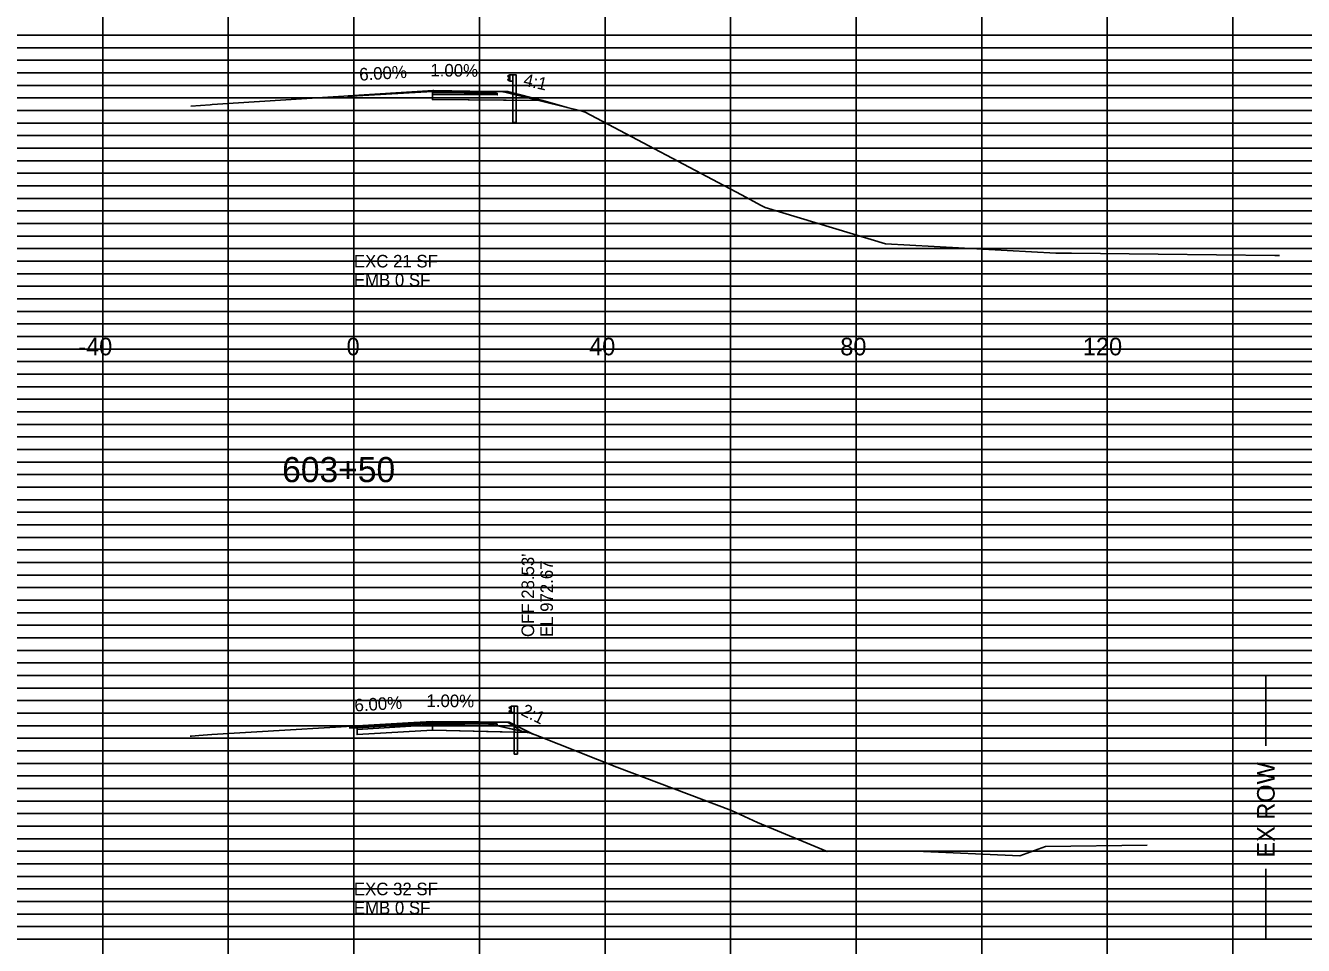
# Model space of a CAD drawing. Extents: x 2313580 to 2322968, y 282099 to 303247.
# Drawn here: x 2318731.4 to 2318934.9, y 287726.7 to 287873.2 of the extents above; entities that cross this region are included whole.
import ezdxf

# ---------------------------------------------------------------- set-up
doc = ezdxf.new("R2010")
doc.units = 0
for name, color, linetype in [('DESIGN - CENTERLINE - Proposed', 7, 'Continuous'), ('DESIGN - DRAINAGE - Text', 7, 'Continuous'), ('DESIGN - EARTHWORK - Excavation Limit Lines', 7, 'Continuous'), ('DESIGN - EARTHWORK - Shapes', 7, 'Continuous'), ('DESIGN - SCRATCH - User 1', 7, 'Continuous'), ('DESIGN - SHEET - Light Grid', 7, 'Continuous'), ('DESIGN - SHEET - Linework', 7, 'Continuous'), ('DESIGN - TYPICAL - Finished Grade and Subgrade', 7, 'Continuous'), ('DESIGN - TYPICAL - Finished Grade Slopes Text', 7, 'Continuous'), ('DESIGN - TYPICAL - Guardrail', 7, 'Continuous'), ('DESIGN - TYPICAL - Text', 7, 'Continuous'), ('Scratch Level', 7, 'Continuous'), ('SURVEY - GROUND - Top of Ground', 7, 'Continuous'), ('SURVEY - PROPERTY - ROW Lines Text', 7, 'Continuous')]:
    doc.layers.add(name, color=color, linetype=linetype)

# ---------------------------------------------------------------- blocks, each defined once
blk = doc.blocks.new('GRTYP')
at = {"layer": 'DESIGN - CENTERLINE - Proposed'}
for p, q in [((0.162, 0.37), (0.162, 0.37)), ((0.162, 0.37), (0.162, 0.37)), ((0.264, 0.37), (0.264, 0.37)), ((0.264, 0.37), (0.264, 0.37))]:
    blk.add_line(p, q, dxfattribs=at)
for points in [[(0.059, 0.567), (0.04, 0.563), (0.004, 0.539), (0, 0.531), (0.004, 0.523), (0.055, 0.492), (0.059, 0.484), (0.059, 0.464), (0.055, 0.456), (0.004, 0.425), (0, 0.417), (0.004, 0.409), (0.04, 0.385), (0.059, 0.382)], [(0.162, 0.374), (0.059, 0.374), (0.059, 0.574), (0.162, 0.574)], [(0.264, -0.126), (0.264, 0.574), (0.162, 0.574), (0.162, -0.075)], [(0.162, -0.075), (0.162, -0.949), (0.264, -0.949), (0.264, -0.122)]]:
    blk.add_lwpolyline(points, dxfattribs=at)

msp = doc.modelspace()

# ---------------------------------------------------------------- linework, layer by layer
msp.add_line((2318796.2, 287862.24), (2318806.51, 287862.15))
at = {"layer": 'DESIGN - EARTHWORK - Shapes'}
for points in [[(2318782.75, 287861.99), (2318795.48, 287862.8), (2318796.26, 287862.85), (2318796.41, 287862.84), (2318802.13, 287862.74), (2318807.38, 287862.64), (2318807.53, 287862.64), (2318807.94, 287862.56), (2318813.17, 287861.25), (2318796.2, 287861.41), (2318796.2, 287862.24), (2318796.2, 287862.49), (2318796.2, 287862.7), (2318784.2, 287861.98), (2318782.75, 287861.89)], [(2318813.17, 287861.25), (2318817.64, 287860.14), (2318813.77, 287861.25)], [(2318783.06, 287761.57), (2318791.5, 287762.07), (2318794.35, 287762.24), (2318804.18, 287762.1), (2318804.63, 287762.1), (2318804.66, 287762.09), (2318811.26, 287760.61), (2318796.19, 287760.97), (2318784.19, 287760.25), (2318784.19, 287761.08), (2318784.19, 287761.33), (2318783.06, 287761.27), (2318783.06, 287761.47)], [(2318811.26, 287760.61), (2318811.84, 287760.48), (2318812.21, 287760.34), (2318811.7, 287760.6)]]:
    msp.add_lwpolyline(points, close=True, dxfattribs=at)
at = {"layer": 'DESIGN - SCRATCH - User 1'}
for points in [[(2318806.2, 287862.7), (2318808.2, 287862.68), (2318810.77, 287861.85)], [(2318806.2, 287862.7), (2318808.2, 287862.68), (2318810.77, 287861.85)], [(2318806.2, 287862.7), (2318808.2, 287862.68), (2318810.77, 287861.85)], [(2318806.2, 287862.7), (2318808.2, 287862.68), (2318810.77, 287861.85)], [(2318806.19, 287762.26), (2318808.19, 287762.24), (2318810.33, 287760.82)], [(2318806.19, 287762.26), (2318808.19, 287762.24), (2318810.33, 287760.82)], [(2318806.19, 287762.26), (2318808.19, 287762.24), (2318810.33, 287760.82)], [(2318806.19, 287762.26), (2318808.19, 287762.24), (2318810.33, 287760.82)]]:
    msp.add_lwpolyline(points, dxfattribs=at)
at = {"layer": 'DESIGN - SHEET - Light Grid'}
for p, q in [((2318623.68, 287871.67), (2318783.68, 287871.67)), ((2318783.68, 287871.67), (2318943.68, 287871.67)), ((2318623.68, 287869.67), (2318783.68, 287869.67)), ((2318783.68, 287869.67), (2318943.68, 287869.67)), ((2318623.68, 287865.67), (2318783.68, 287865.67)), ((2318783.68, 287865.67), (2318943.68, 287865.67)), ((2318623.68, 287863.67), (2318783.68, 287863.67)), ((2318783.68, 287863.67), (2318943.68, 287863.67)), ((2318623.68, 287861.67), (2318783.68, 287861.67)), ((2318783.68, 287861.67), (2318943.68, 287861.67)), ((2318623.68, 287859.67), (2318783.68, 287859.67)), ((2318783.68, 287859.67), (2318943.68, 287859.67)), ((2318623.68, 287857.67), (2318783.68, 287857.67)), ((2318783.68, 287857.67), (2318943.68, 287857.67)), ((2318623.68, 287855.67), (2318783.68, 287855.67)), ((2318783.68, 287855.67), (2318943.68, 287855.67)), ((2318623.68, 287853.67), (2318783.68, 287853.67)), ((2318783.68, 287853.67), (2318943.68, 287853.67)), ((2318623.68, 287851.67), (2318783.68, 287851.67)), ((2318783.68, 287851.67), (2318943.68, 287851.67)), ((2318623.68, 287849.67), (2318783.68, 287849.67)), ((2318783.68, 287849.67), (2318943.68, 287849.67)), ((2318623.68, 287845.67), (2318783.68, 287845.67)), ((2318783.68, 287845.67), (2318943.68, 287845.67)), ((2318623.68, 287843.67), (2318783.68, 287843.67)), ((2318783.68, 287843.67), (2318943.68, 287843.67)), ((2318623.68, 287841.67), (2318783.68, 287841.67)), ((2318783.68, 287841.67), (2318943.68, 287841.67)), ((2318623.68, 287839.67), (2318783.68, 287839.67)), ((2318783.68, 287839.67), (2318943.68, 287839.67)), ((2318623.68, 287837.67), (2318783.68, 287837.67)), ((2318783.68, 287837.67), (2318943.68, 287837.67)), ((2318623.68, 287835.67), (2318783.68, 287835.67)), ((2318783.68, 287835.67), (2318943.68, 287835.67)), ((2318623.68, 287833.67), (2318783.68, 287833.67)), ((2318783.68, 287833.67), (2318943.68, 287833.67)), ((2318623.68, 287831.67), (2318783.68, 287831.67)), ((2318783.68, 287831.67), (2318943.68, 287831.67)), ((2318623.68, 287829.67), (2318783.68, 287829.67)), ((2318783.68, 287829.67), (2318943.68, 287829.67)), ((2318623.68, 287825.67), (2318783.68, 287825.67)), ((2318783.68, 287825.67), (2318943.68, 287825.67)), ((2318623.68, 287823.67), (2318783.68, 287823.67)), ((2318783.68, 287823.67), (2318943.68, 287823.67)), ((2318623.68, 287821.67), (2318783.68, 287821.67)), ((2318783.68, 287821.67), (2318943.68, 287821.67)), ((2318623.68, 287819.67), (2318783.68, 287819.67)), ((2318783.68, 287819.67), (2318943.68, 287819.67)), ((2318623.68, 287817.67), (2318783.68, 287817.67)), ((2318783.68, 287817.67), (2318943.68, 287817.67)), ((2318623.68, 287815.67), (2318783.68, 287815.67)), ((2318783.68, 287815.67), (2318943.68, 287815.67)), ((2318623.68, 287813.67), (2318783.68, 287813.67)), ((2318623.68, 287811.67), (2318783.68, 287811.67)), ((2318783.68, 287813.67), (2318943.68, 287813.67)), ((2318783.68, 287811.67), (2318943.68, 287811.67)), ((2318623.68, 287809.67), (2318783.68, 287809.67)), ((2318783.68, 287809.67), (2318943.68, 287809.67)), ((2318623.68, 287805.67), (2318783.68, 287805.67)), ((2318783.68, 287805.67), (2318943.68, 287805.67)), ((2318623.68, 287803.67), (2318783.68, 287803.67)), ((2318783.68, 287803.67), (2318943.68, 287803.67)), ((2318623.68, 287801.67), (2318783.68, 287801.67)), ((2318783.68, 287801.67), (2318943.68, 287801.67)), ((2318623.68, 287799.67), (2318783.68, 287799.67)), ((2318783.68, 287799.67), (2318943.68, 287799.67)), ((2318623.68, 287797.67), (2318783.68, 287797.67)), ((2318783.68, 287797.67), (2318943.68, 287797.67)), ((2318623.68, 287795.67), (2318783.68, 287795.67)), ((2318783.68, 287795.67), (2318943.68, 287795.67)), ((2318623.68, 287793.67), (2318783.68, 287793.67)), ((2318783.68, 287793.67), (2318943.68, 287793.67)), ((2318623.68, 287791.67), (2318783.68, 287791.67)), ((2318783.68, 287791.67), (2318943.68, 287791.67)), ((2318623.68, 287789.67), (2318783.68, 287789.67)), ((2318783.68, 287789.67), (2318943.68, 287789.67)), ((2318623.68, 287785.67), (2318783.68, 287785.67)), ((2318783.68, 287785.67), (2318943.68, 287785.67)), ((2318623.68, 287783.67), (2318783.68, 287783.67)), ((2318783.68, 287783.67), (2318943.68, 287783.67)), ((2318623.68, 287781.67), (2318783.68, 287781.67)), ((2318783.68, 287781.67), (2318943.68, 287781.67)), ((2318623.68, 287779.67), (2318783.68, 287779.67)), ((2318783.68, 287779.67), (2318943.68, 287779.67)), ((2318623.68, 287777.67), (2318783.68, 287777.67)), ((2318783.68, 287777.67), (2318943.68, 287777.67)), ((2318623.68, 287775.67), (2318783.68, 287775.67)), ((2318783.68, 287775.67), (2318943.68, 287775.67)), ((2318623.68, 287773.67), (2318783.68, 287773.67)), ((2318783.68, 287773.67), (2318943.68, 287773.67)), ((2318623.68, 287771.67), (2318783.68, 287771.67)), ((2318783.68, 287771.67), (2318943.68, 287771.67)), ((2318623.68, 287769.67), (2318783.68, 287769.67)), ((2318783.68, 287769.67), (2318943.68, 287769.67)), ((2318623.68, 287765.67), (2318783.68, 287765.67)), ((2318783.68, 287765.67), (2318943.68, 287765.67)), ((2318623.68, 287763.67), (2318783.68, 287763.67)), ((2318783.68, 287763.67), (2318943.68, 287763.67)), ((2318623.68, 287761.67), (2318783.68, 287761.67)), ((2318783.68, 287761.67), (2318943.68, 287761.67)), ((2318623.68, 287759.67), (2318783.68, 287759.67)), ((2318783.68, 287759.67), (2318943.68, 287759.67)), ((2318623.68, 287757.67), (2318783.68, 287757.67)), ((2318783.68, 287757.67), (2318943.68, 287757.67)), ((2318623.68, 287755.67), (2318783.68, 287755.67)), ((2318783.68, 287755.67), (2318943.68, 287755.67)), ((2318623.68, 287753.67), (2318783.68, 287753.67)), ((2318783.68, 287753.67), (2318943.68, 287753.67)), ((2318623.68, 287751.67), (2318783.68, 287751.67)), ((2318783.68, 287751.67), (2318943.68, 287751.67)), ((2318623.68, 287749.67), (2318783.68, 287749.67)), ((2318783.68, 287749.67), (2318943.68, 287749.67)), ((2318623.68, 287745.67), (2318783.68, 287745.67)), ((2318783.68, 287745.67), (2318943.68, 287745.67)), ((2318623.68, 287743.67), (2318783.68, 287743.67)), ((2318783.68, 287743.67), (2318943.68, 287743.67)), ((2318623.68, 287741.67), (2318783.68, 287741.67)), ((2318783.68, 287741.67), (2318943.68, 287741.67)), ((2318623.68, 287739.67), (2318783.68, 287739.67)), ((2318783.68, 287739.67), (2318943.68, 287739.67)), ((2318623.68, 287737.67), (2318783.68, 287737.67)), ((2318783.68, 287737.67), (2318943.68, 287737.67)), ((2318623.68, 287735.67), (2318783.68, 287735.67)), ((2318783.68, 287735.67), (2318943.68, 287735.67)), ((2318623.68, 287733.67), (2318783.68, 287733.67)), ((2318783.68, 287733.67), (2318943.68, 287733.67)), ((2318623.68, 287731.67), (2318783.68, 287731.67)), ((2318783.68, 287731.67), (2318943.68, 287731.67)), ((2318623.68, 287729.67), (2318783.68, 287729.67)), ((2318783.68, 287729.67), (2318943.68, 287729.67))]:
    msp.add_line(p, q, dxfattribs=at)
at = {"layer": 'DESIGN - SHEET - Linework'}
for p, q in [((2318743.68, 287587.67), (2318743.68, 288007.67)), ((2318763.68, 287587.67), (2318763.68, 288007.67)), ((2318783.68, 287587.67), (2318783.68, 288007.67)), ((2318803.68, 287587.67), (2318803.68, 288007.67)), ((2318823.68, 287587.67), (2318823.68, 288007.67)), ((2318843.68, 287587.67), (2318843.68, 288007.67)), ((2318863.68, 287587.67), (2318863.68, 288007.67)), ((2318883.68, 287587.67), (2318883.68, 288007.67)), ((2318903.68, 287587.67), (2318903.68, 288007.67)), ((2318923.68, 287587.67), (2318923.68, 288007.67)), ((2318463.68, 287867.67), (2319103.68, 287867.67)), ((2318463.68, 287847.67), (2319103.68, 287847.67)), ((2318463.68, 287827.67), (2319103.68, 287827.67)), ((2318463.68, 287807.67), (2319103.68, 287807.67)), ((2318463.68, 287787.67), (2319103.68, 287787.67)), ((2318463.68, 287767.67), (2319103.68, 287767.67)), ((2318463.68, 287747.67), (2319103.68, 287747.67)), ((2318463.68, 287727.67), (2319103.68, 287727.67))]:
    msp.add_line(p, q, dxfattribs=at)
at = {"layer": 'DESIGN - TYPICAL - Finished Grade and Subgrade'}
for points in [[(2318782.75, 287861.99), (2318784.02, 287862.07), (2318784.2, 287862.08), (2318794.7, 287862.71), (2318796.2, 287862.8), (2318804.95, 287862.72), (2318806.2, 287862.7), (2318807.95, 287862.69), (2318808.2, 287862.68), (2318808.49, 287862.61), (2318813.77, 287861.25), (2318817.64, 287860.14)], [(2318783.06, 287761.57), (2318783.34, 287761.59), (2318784.19, 287761.64), (2318793.21, 287762.18), (2318796.19, 287762.36), (2318803.7, 287762.29), (2318806.19, 287762.26), (2318807.69, 287762.25), (2318808.42, 287762.24), (2318812.21, 287760.34)]]:
    msp.add_lwpolyline(points, dxfattribs=at)
for points in [[(2318784.2, 287862.08), (2318796.2, 287862.8), (2318796.2, 287862.7), (2318784.2, 287861.98)], [(2318796.2, 287862.8), (2318806.2, 287862.7), (2318806.2, 287862.6), (2318796.2, 287862.7)], [(2318796.2, 287862.24), (2318806.51, 287862.15), (2318806.51, 287862.4), (2318806.3, 287862.4), (2318806.3, 287862.6), (2318806.2, 287862.6), (2318806.2, 287862.7), (2318808.2, 287862.68), (2318813.77, 287861.25), (2318796.2, 287861.41)], [(2318796.2, 287862.7), (2318806.3, 287862.6), (2318806.3, 287862.4), (2318796.2, 287862.49)], [(2318784.2, 287862.08), (2318782.75, 287861.99), (2318782.75, 287861.89), (2318784.2, 287861.98)], [(2318796.2, 287862.49), (2318806.51, 287862.4), (2318806.51, 287862.15), (2318796.2, 287862.24)], [(2318784.19, 287761.64), (2318783.06, 287761.57), (2318783.06, 287761.47), (2318784.19, 287761.54)], [(2318784.19, 287761.54), (2318784.19, 287761.33), (2318783.06, 287761.27), (2318783.06, 287761.47)], [(2318784.19, 287761.64), (2318796.19, 287762.36), (2318796.19, 287762.26), (2318784.19, 287761.54)], [(2318784.19, 287761.54), (2318796.19, 287762.26), (2318796.19, 287762.05), (2318784.19, 287761.33)], [(2318784.19, 287761.33), (2318796.19, 287762.05), (2318796.19, 287761.8), (2318784.19, 287761.08)], [(2318784.19, 287761.08), (2318796.19, 287761.8), (2318796.19, 287760.97), (2318784.19, 287760.25)], [(2318796.19, 287762.36), (2318806.19, 287762.26), (2318806.19, 287762.16), (2318796.19, 287762.26)], [(2318796.19, 287761.8), (2318806.5, 287761.71), (2318806.5, 287761.96), (2318806.29, 287761.96), (2318806.29, 287762.16), (2318806.19, 287762.16), (2318806.19, 287762.26), (2318808.42, 287762.24), (2318811.7, 287760.6), (2318796.19, 287760.97)], [(2318796.19, 287762.26), (2318806.29, 287762.16), (2318806.29, 287761.96), (2318796.19, 287762.05)], [(2318796.19, 287762.05), (2318806.5, 287761.96), (2318806.5, 287761.71), (2318796.19, 287761.8)]]:
    msp.add_lwpolyline(points, close=True, dxfattribs=at)
at = {"layer": 'Scratch Level'}
for points in [[(2318782.75, 287861.99), (2318795.48, 287862.8), (2318796.26, 287862.85), (2318796.41, 287862.84), (2318802.13, 287862.74), (2318807.38, 287862.64), (2318807.53, 287862.64), (2318807.94, 287862.56), (2318813.17, 287861.25), (2318796.2, 287861.41), (2318796.2, 287862.24), (2318796.2, 287862.49), (2318796.2, 287862.7), (2318784.2, 287861.98), (2318782.75, 287861.89)], [(2318813.17, 287861.25), (2318817.64, 287860.14), (2318813.77, 287861.25)], [(2318783.06, 287761.57), (2318791.5, 287762.07), (2318794.35, 287762.24), (2318804.18, 287762.1), (2318804.63, 287762.1), (2318804.66, 287762.09), (2318811.26, 287760.61), (2318796.19, 287760.97), (2318784.19, 287760.25), (2318784.19, 287761.08), (2318784.19, 287761.33), (2318783.06, 287761.27), (2318783.06, 287761.47)], [(2318811.26, 287760.61), (2318811.84, 287760.48), (2318812.21, 287760.34), (2318811.7, 287760.6)]]:
    msp.add_lwpolyline(points, close=True, dxfattribs=at)
at = {"layer": 'SURVEY - GROUND - Top of Ground'}
for points in [[(2318757.69, 287860.35), (2318757.74, 287860.34), (2318760.81, 287860.59), (2318761.11, 287860.61), (2318795.48, 287862.8), (2318796.26, 287862.85), (2318796.41, 287862.84), (2318802.13, 287862.74), (2318807.38, 287862.64), (2318807.53, 287862.64), (2318807.94, 287862.56), (2318820.05, 287859.54), (2318820.53, 287859.39), (2318845.43, 287846.21), (2318848.57, 287844.51), (2318849.19, 287844.22), (2318868.33, 287838.44), (2318895.47, 287836.97), (2318897.6, 287836.92), (2318897.96, 287836.92), (2318911.78, 287836.76), (2318930.34, 287836.58), (2318931.11, 287836.57)], [(2318757.63, 287760.01), (2318757.8, 287760), (2318759.01, 287760.1), (2318761.08, 287760.26), (2318791.5, 287762.07), (2318794.35, 287762.24), (2318804.18, 287762.1), (2318804.63, 287762.1), (2318804.66, 287762.09), (2318811.84, 287760.48), (2318813.22, 287759.97), (2318825.56, 287755.05), (2318843.81, 287748.16), (2318847.95, 287746.26), (2318859.07, 287741.63), (2318873.25, 287741.69), (2318889.75, 287740.96), (2318893.86, 287742.45), (2318910.05, 287742.67)]]:
    msp.add_lwpolyline(points, dxfattribs=at)
at = {"layer": 'SURVEY - PROPERTY - ROW Lines Text'}
for p, q in [((2318928.93, 287769.67), (2318928.93, 287758.47)), ((2318928.93, 287727.67), (2318928.93, 287738.87))]:
    msp.add_line(p, q, dxfattribs=at)

# ---------------------------------------------------------------- block references
at = {"layer": 'DESIGN - TYPICAL - Guardrail', "xscale": 5, "yscale": 5}
for p in [(2318808.2, 287862.49), (2318808.42, 287761.89)]:
    msp.add_blockref('GRTYP', p, dxfattribs=at)

# ---------------------------------------------------------------- texts
at = {"layer": 'DESIGN - DRAINAGE - Text'}
for s, p in [("OFF 28.53'", (2318812.39, 287775.8)), ('EL 972.67', (2318815.39, 287775.8))]:
    msp.add_text(s, height=2, rotation=90, dxfattribs=at).set_placement(p)
at = {"layer": 'DESIGN - EARTHWORK - Excavation Limit Lines'}
for s, p in [('EXC 21 SF', (2318783.68, 287834.67)), ('EMB 0 SF', (2318783.68, 287831.67)), ('EXC 32 SF', (2318783.68, 287734.67)), ('EMB 0 SF', (2318783.68, 287731.67))]:
    msp.add_text(s, height=2, dxfattribs=at).set_placement(p)
at = {"layer": 'DESIGN - TYPICAL - Finished Grade Slopes Text'}
for s, rotation, p in [('6.00%', 3.434, (2318784.59, 287864.41)), ('1.00%', 359.4274, (2318795.86, 287865.11)), ('4:1', 347.1222, (2318810.57, 287863.67)), ('6.00%', 3.4339, (2318783.84, 287763.92)), ('1.00%', 359.4273, (2318795.24, 287764.67)), ('2:1', 333.8029, (2318810.15, 287763.45))]:
    msp.add_text(s, height=2, rotation=rotation, dxfattribs=at).set_placement(p)
at = {"layer": 'DESIGN - TYPICAL - Text'}
for s, height, p in [('-40', 2.8, (2318739.79, 287820.67)), ('0', 2.8, (2318782.52, 287820.67)), ('40', 2.8, (2318821.15, 287820.67)), ('80', 2.8, (2318861.15, 287820.67)), ('120', 2.8, (2318899.79, 287820.67)), ('603+50', 4, (2318772.26, 287800.47))]:
    msp.add_text(s, height=height, dxfattribs=at).set_placement(p)
at = {"layer": 'SURVEY - PROPERTY - ROW Lines Text'}
msp.add_text('EX ROW', height=2.8, rotation=90, dxfattribs=at).set_placement((2318930.33, 287740.67))

doc.saveas('drawing.dxf')
